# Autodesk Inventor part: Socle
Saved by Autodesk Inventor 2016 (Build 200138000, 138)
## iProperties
Created: 2013-08
Part Number: Socle
Material: Générique
Document SubType Name: Modeling
Designer: hilarion
Density: 1 g/cm^3
Appearance: Par défaut
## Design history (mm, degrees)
node "Socle1"
node "Socle"
node "Base1"
